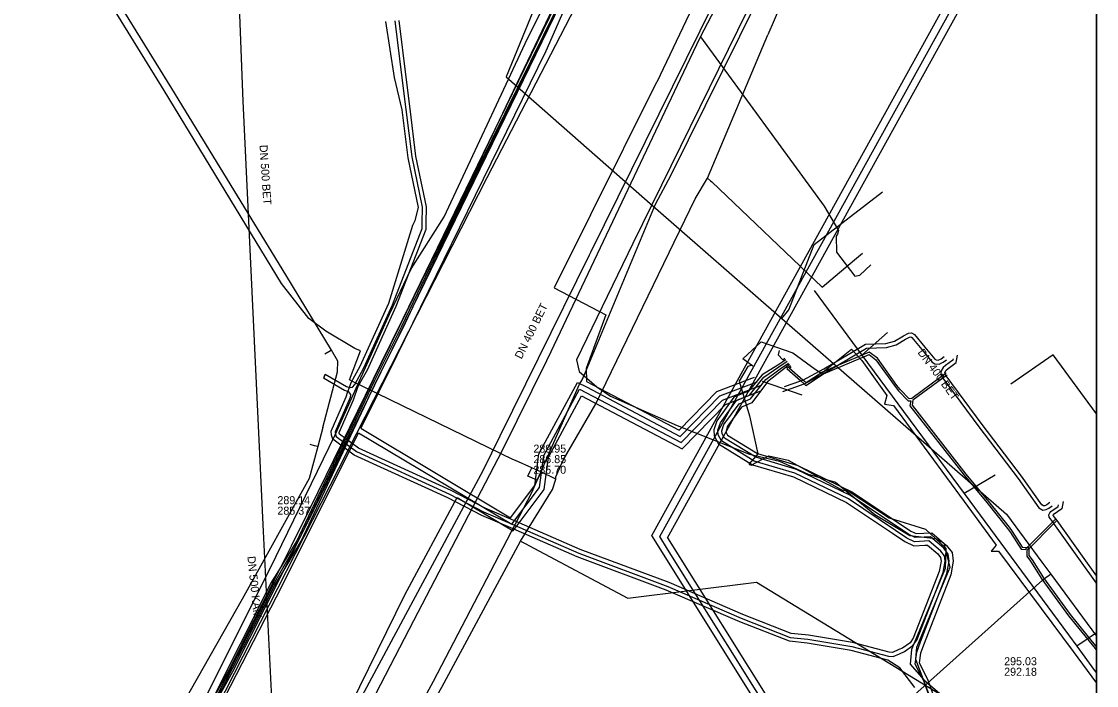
# Model space of a CAD drawing. Extents: x -598233 to -596890, y -1157848 to -1156431.
# Drawn here: x -596997.9 to -596890.5, y -1156890.3 to -1156824 of the extents above; entities that cross this region are included whole.
import ezdxf

# ---------------------------------------------------------------- set-up
doc = ezdxf.new("R2010")
doc.units = 0
for name, color, linetype in [('Vrstva 12', 7, 'Continuous'), ('Vrstva 13', 7, 'Continuous'), ('Vrstva 19', 7, 'Continuous'), ('Vrstva 25', 7, 'Continuous'), ('Vrstva 26', 7, 'Continuous'), ('Vrstva 37', 7, 'Continuous'), ('Vrstva 42', 7, 'Continuous'), ('Vrstva 44', 7, 'Continuous'), ('Vrstva 55', 7, 'Continuous'), ('Vrstva 58', 7, 'Continuous'), ('Vrstva 60', 7, 'Continuous'), ('Vrstva 9', 7, 'Continuous'), ('zajmove_uzemi', 7, 'Continuous')]:
    doc.layers.add(name, color=color, linetype=linetype)

msp = doc.modelspace()

# ---------------------------------------------------------------- linework, layer by layer
at = {"layer": 'Vrstva 12'}
for points in [[(-596930.04, -1156825.5), (-596919.76, -1156805.9), (-596915.21, -1156798.19), (-596910.25, -1156789.71), (-596903.15, -1156779.71)], [(-596963.84, -1156893.76), (-596958.67, -1156883.83), (-596949.82, -1156866.8), (-596945.38, -1156857.84), (-596944.95, -1156856.94), (-596931.11, -1156827.75), (-596930.04, -1156825.5)], [(-596930.04, -1156825.5), (-596917.68, -1156842.43), (-596916.25, -1156844.85)], [(-596916.25, -1156844.85), (-596916.35, -1156845.24)], [(-596916.35, -1156845.24), (-596916.49, -1156845.42), (-596916.43, -1156847.03), (-596914.6, -1156849.41), (-596914.12, -1156849.32), (-596913.02, -1156848.28)]]:
    msp.add_lwpolyline(points, dxfattribs=at)
at = {"layer": 'Vrstva 13'}
for p, q in [((-596966.91, -1156856.8), (-596967.18, -1156856.98)), ((-596967.18, -1156856.98), (-596967.58, -1156857.23)), ((-596968.59, -1156866.37), (-596969.05, -1156866.25)), ((-596968.28, -1156866.45), (-596968.59, -1156866.37))]:
    msp.add_line(p, q, dxfattribs=at)
for points in [[(-596938.76, -1156803.44), (-596938.92, -1156803.8), (-596947.54, -1156824.9), (-596949.46, -1156829.5), (-596934.8, -1156842.4)], [(-596967.78, -1156864.53), (-596966.32, -1156858.99), (-596966.27, -1156857.91), (-596966.91, -1156856.8), (-596971.48, -1156849.28), (-596982.85, -1156830.68), (-596992.24, -1156815.47)], [(-596921.9, -1156853.64), (-596921.2, -1156852.79), (-596918.66, -1156846.27), (-596911.84, -1156841.01)], [(-596934.8, -1156842.4), (-596921.9, -1156853.64), (-596899.46, -1156873.19), (-596895.91, -1156878), (-596895.03, -1156879.2), (-596890.46, -1156885.4)], [(-596967.78, -1156864.53), (-596968.28, -1156866.45), (-596969.12, -1156869.63), (-596975.82, -1156881.68), (-596987.36, -1156902), (-596995.97, -1156916.01), (-597005.76, -1156929.74), (-597017.4, -1156942.73), (-597033.49, -1156958.74), (-597059.77, -1156983.91), (-597076.36, -1156999.81), (-597090.23, -1157012.97), (-597109.08, -1157030.59), (-597111.35, -1157034.13), (-597112.48, -1157035.47), (-597112.98, -1157036.09)], [(-596895.03, -1156879.2), (-596895.19, -1156879.31), (-596895.86, -1156879.78), (-596910.55, -1156892.94)]]:
    msp.add_lwpolyline(points, dxfattribs=at)
at = {"layer": 'Vrstva 19'}
for points in [[(-596890.46, -1156772.16), (-596894.96, -1156777.24), (-596902.9, -1156787.67), (-596916.35, -1156810.75), (-596921.34, -1156820.69), (-596921.42, -1156820.88), (-596923.29, -1156825.32)], [(-596948.53, -1156867.85), (-596948.8, -1156867.73), (-596964.74, -1156859.99), (-596965.12, -1156859.79), (-596963.99, -1156856.87), (-596964.57, -1156856.65), (-596967.48, -1156854.93), (-596969.17, -1156853.66), (-596971.89, -1156850.17), (-596983.64, -1156830.87), (-596992.65, -1156816.23), (-597003.25, -1156798.44), (-597029.14, -1156797.81), (-597057.59, -1156797.99), (-597061.06, -1156797.77), (-597071.98, -1156796.79), (-597087.41, -1156795.86), (-597102.05, -1156795.07), (-597103.22, -1156797.72)], [(-596944.5, -1156869.71), (-596944.5, -1156869.48), (-596943.75, -1156867.82), (-596940.5, -1156862.16), (-596930.57, -1156841.71), (-596929.34, -1156839.64), (-596923.29, -1156825.32)], [(-596929.34, -1156839.64), (-596929.02, -1156839.89), (-596928.91, -1156839.99), (-596917.88, -1156850.52), (-596914.63, -1156847.8)], [(-596914.63, -1156847.8), (-596913.85, -1156847.14)], [(-596946.45, -1156868.78), (-596946.9, -1156868.57), (-596948.53, -1156867.85)], [(-596945.99, -1156868.98), (-596946.17, -1156869.39), (-596946.36, -1156869.8), (-596947.27, -1156869.4), (-596947.09, -1156868.98), (-596946.9, -1156868.57)], [(-596944.5, -1156869.71), (-596945.99, -1156868.98), (-596946.45, -1156868.78)], [(-597070.67, -1157028.24), (-597069.06, -1157026.66), (-597068.04, -1157025.67), (-597047.41, -1157005.47), (-596990.41, -1156944.69), (-596980.1, -1156930.5), (-596969.41, -1156912.52), (-596962.33, -1156901.94), (-596955.88, -1156890.47), (-596948.03, -1156875.88), (-596944.82, -1156870.73), (-596944.5, -1156869.71)], [(-596948.03, -1156875.88), (-596947.63, -1156876.1)], [(-596947.63, -1156876.1), (-596947.41, -1156876.21)], [(-596947.41, -1156876.21), (-596947.19, -1156876.33)], [(-596947.19, -1156876.33), (-596937.31, -1156881.6), (-596924.45, -1156879.98), (-596904.63, -1156892.09), (-596901.11, -1156896.6), (-596899.26, -1156898.5), (-596890.46, -1156911.36)]]:
    msp.add_lwpolyline(points, dxfattribs=at)
at = {"layer": 'Vrstva 25'}
msp.add_line((-596934.11, -1156875.44), (-596903.03, -1156819.22), dxfattribs=at)
msp.add_lwpolyline([(-596921.58, -1156895.47), (-596933.32, -1156876.7), (-596934.11, -1156875.44)], dxfattribs=at)
at = {"layer": 'Vrstva 26'}
for p, q in [((-596934.89, -1156875.32), (-596903.33, -1156818.2)), ((-596933.32, -1156875.57), (-596902.74, -1156820.24)), ((-596921.74, -1156896.34), (-596934.89, -1156875.32)), ((-596933.32, -1156875.57), (-596921.41, -1156894.6))]:
    msp.add_line(p, q, dxfattribs=at)
at = {"layer": 'Vrstva 37'}
msp.add_lwpolyline([(-596890.46, -1156863.18), (-596894.78, -1156857.28), (-596899.01, -1156860.21)], dxfattribs=at)
at = {"layer": 'Vrstva 42'}
for points in [[(-596967.62, -1156859.4), (-596967.54, -1156859.22), (-596965.4, -1156860.46), (-596965.12, -1156860.54), (-596965.04, -1156860.56), (-596964.79, -1156860.51), (-596964.58, -1156860.23), (-596963.67, -1156858.59), (-596960.8, -1156852.28), (-596957.85, -1156844.66), (-596957.85, -1156844.13), (-596957.8, -1156842.53), (-596958.86, -1156837.52), (-596959.44, -1156832.77), (-596959.85, -1156829.61), (-596960.54, -1156823.91)], [(-596910.21, -1156886.73), (-596910.84, -1156887.01), (-596911.17, -1156886.98), (-596914.83, -1156886.03), (-596919.25, -1156885.3), (-596920.96, -1156885.11), (-596925.81, -1156883.22), (-596933.16, -1156880.04), (-596942.04, -1156876.72), (-596948.68, -1156873.84), (-596951.55, -1156872.61), (-596954.93, -1156870.85), (-596964.22, -1156866.61), (-596966.1, -1156865.2), (-596966.13, -1156865.11), (-596966.14, -1156865.04), (-596964.71, -1156861.77), (-596964.24, -1156860.42), (-596963.32, -1156858.77), (-596960.43, -1156852.43), (-596957.45, -1156844.74), (-596957.45, -1156844.13), (-596957.4, -1156842.49), (-596958.47, -1156837.45), (-596959.05, -1156832.72), (-596959.45, -1156829.56), (-596960.14, -1156823.88)], [(-596959.26, -1156837.59), (-596959.84, -1156832.82), (-596960.6, -1156829.58), (-596961.49, -1156823.97)], [(-596908.6, -1156890.52), (-596910.1, -1156888.56), (-596911.3, -1156887.78), (-596914.99, -1156886.81), (-596919.36, -1156886.09), (-596921.15, -1156885.9), (-596926.11, -1156883.96), (-596933.46, -1156880.79), (-596942.34, -1156877.46), (-596949, -1156874.57), (-596951.89, -1156873.34), (-596955.28, -1156871.57), (-596964.63, -1156867.3), (-596966.76, -1156865.7), (-596966.91, -1156865.3), (-596966.95, -1156864.92), (-596965.45, -1156861.48), (-596965.26, -1156860.95), (-596965.12, -1156860.54), (-596964.94, -1156860.03), (-596964.03, -1156858.4), (-596961.17, -1156852.12), (-596958.77, -1156844.32), (-596958.53, -1156843.87), (-596958.2, -1156842.56), (-596959.26, -1156837.59)], [(-596921.79, -1156860.93), (-596919.67, -1156860.19), (-596919.63, -1156860.18), (-596917.5, -1156859.02), (-596916.49, -1156858.43), (-596914.9, -1156857.49), (-596913.43, -1156856.62), (-596911.46, -1156856.54), (-596910.48, -1156856.28), (-596909.56, -1156855.72), (-596909.14, -1156855.52), (-596909.03, -1156855.5), (-596908.92, -1156855.56), (-596907.92, -1156856.76), (-596906.88, -1156858.01), (-596906.62, -1156858.17), (-596906.19, -1156858.21), (-596905.79, -1156858.02), (-596905.44, -1156857.77)], [(-596921.65, -1156860.46), (-596920.01, -1156859.89), (-596919.8, -1156859.81), (-596919.8, -1156859.81), (-596917.7, -1156858.68), (-596915.1, -1156857.14), (-596913.55, -1156856.22), (-596911.51, -1156856.14), (-596910.64, -1156855.91), (-596909.75, -1156855.37), (-596909.26, -1156855.13), (-596908.96, -1156855.08), (-596908.66, -1156855.24), (-596907.61, -1156856.5), (-596906.61, -1156857.7), (-596906.49, -1156857.78), (-596906.27, -1156857.8), (-596905.99, -1156857.67), (-596905.68, -1156857.45)], [(-596922.18, -1156856.84), (-596922.28, -1156857.29), (-596921.82, -1156857.79), (-596921.6, -1156857.63)], [(-596921.49, -1156857.78), (-596922.32, -1156858.3)], [(-596922.2, -1156858.49), (-596921.37, -1156857.93)], [(-596921.05, -1156858.37), (-596921.42, -1156858.64), (-596920.01, -1156859.89), (-596919.67, -1156860.19), (-596919.5, -1156860.34), (-596917.75, -1156859.18), (-596913.19, -1156857.24), (-596912.5, -1156857.77), (-596910.57, -1156860.45), (-596910.24, -1156860.87), (-596909.27, -1156861.89), (-596909.01, -1156861.87), (-596909.11, -1156862.38), (-596903.68, -1156869.31), (-596901.43, -1156872.04), (-596899.34, -1156874.63), (-596899.05, -1156875.04), (-596898, -1156876.71), (-596897.57, -1156876.72), (-596897.38, -1156876.53), (-596894.83, -1156873.97), (-596894.6, -1156873.74)], [(-596905.49, -1156859.11), (-596905.6, -1156859.19), (-596905.94, -1156859.45), (-596908.93, -1156861.66), (-596909.19, -1156861.69), (-596910.08, -1156860.73), (-596910.41, -1156860.33), (-596912.36, -1156857.63), (-596913.17, -1156857.01), (-596916.49, -1156858.43), (-596917.85, -1156859), (-596919.48, -1156860.09), (-596919.8, -1156859.81), (-596921.16, -1156858.6), (-596920.98, -1156858.48)], [(-596904.8, -1156857.67), (-596904.83, -1156857.82), (-596905.56, -1156858.34), (-596905.78, -1156858.56), (-596906.03, -1156858.95), (-596905.98, -1156859.39), (-596905.94, -1156859.45), (-596905.82, -1156859.61), (-596902.21, -1156864.47), (-596898.28, -1156869.63), (-596896.22, -1156872.56), (-596895.83, -1156872.8), (-596895.48, -1156872.73), (-596895.24, -1156872.61), (-596894.89, -1156872.36)], [(-596895.13, -1156872.04), (-596895.44, -1156872.27), (-596895.61, -1156872.35), (-596895.75, -1156872.37), (-596895.94, -1156872.26), (-596897.95, -1156869.39), (-596901.89, -1156864.23), (-596905.5, -1156859.37), (-596905.6, -1156859.24), (-596905.6, -1156859.19), (-596905.62, -1156859.05), (-596905.47, -1156858.81), (-596905.3, -1156858.65), (-596904.47, -1156858.06), (-596904.34, -1156857.33)], [(-596922.32, -1156858.3), (-596923.86, -1156859.27), (-596925.25, -1156860.91), (-596926.69, -1156861.52), (-596928.41, -1156863.87), (-596928.69, -1156864.76), (-596928.67, -1156865.38), (-596928.22, -1156866.16), (-596924.84, -1156868.26), (-596920.73, -1156869.47), (-596915.44, -1156872.03), (-596910.85, -1156875.11)], [(-596910.56, -1156874.82), (-596915.24, -1156871.68), (-596920.59, -1156869.09), (-596924.68, -1156867.89), (-596927.92, -1156865.87), (-596928.27, -1156865.27), (-596928.29, -1156864.81), (-596928.05, -1156864.06), (-596926.43, -1156861.85), (-596925.14, -1156861.3), (-596923.69, -1156859.5), (-596922.2, -1156858.49)], [(-596907.11, -1156891.56), (-596907.72, -1156889.83), (-596908.57, -1156888.18), (-596908.4, -1156886.98), (-596908.06, -1156885.96), (-596905.41, -1156879.14), (-596905.18, -1156877.89), (-596905.28, -1156877.2), (-596905.73, -1156876.61), (-596907.06, -1156875.46), (-596907.68, -1156875.5), (-596908.57, -1156875.54), (-596909.21, -1156875.24), (-596915.04, -1156871.33), (-596920.44, -1156868.72), (-596924.51, -1156867.52), (-596927.63, -1156865.59), (-596927.87, -1156865.16), (-596927.89, -1156864.86), (-596927.69, -1156864.24), (-596926.17, -1156862.17), (-596925.02, -1156861.68), (-596923.52, -1156859.74), (-596922.06, -1156858.69)], [(-596921.94, -1156858.87), (-596923.35, -1156859.97), (-596924.91, -1156862.07), (-596925.92, -1156862.5), (-596927.33, -1156864.42), (-596927.48, -1156864.92), (-596927.48, -1156865.04), (-596927.33, -1156865.3), (-596924.35, -1156867.15), (-596920.3, -1156868.34), (-596914.84, -1156870.99), (-596909.02, -1156874.89), (-596908.49, -1156875.14), (-596907.7, -1156875.1), (-596906.93, -1156875.05), (-596905.44, -1156876.33), (-596904.9, -1156877.04), (-596904.77, -1156877.9), (-596905.02, -1156879.25), (-596907.69, -1156886.11), (-596908.04, -1156887.07), (-596908.18, -1156888.06), (-596907.36, -1156889.67), (-596906.72, -1156891.46)], [(-596922.06, -1156858.69), (-596921.25, -1156858.1)], [(-596921.15, -1156858.24), (-596921.94, -1156858.87)], [(-596967.62, -1156859.4), (-596967.71, -1156859.58), (-596965.6, -1156860.81), (-596965.26, -1156860.95), (-596965.24, -1156860.95), (-596964.99, -1156861.24), (-596965.04, -1156861.53), (-596966.54, -1156864.98), (-596966.52, -1156865.21), (-596966.43, -1156865.45), (-596964.42, -1156866.95), (-596955.11, -1156871.21), (-596951.72, -1156872.98), (-596948.84, -1156874.2), (-596942.19, -1156877.09), (-596933.31, -1156880.41), (-596925.96, -1156883.59), (-596921.06, -1156885.51), (-596919.31, -1156885.7), (-596914.91, -1156886.42), (-596911.23, -1156887.38), (-596910.77, -1156887.41), (-596910.15, -1156887.14)], [(-596905.37, -1156859.27), (-596905.5, -1156859.37), (-596905.82, -1156859.61), (-596908.8, -1156861.82), (-596908.89, -1156862.32), (-596903.52, -1156869.19), (-596901.27, -1156871.92), (-596899.18, -1156874.51), (-596898.88, -1156874.93), (-596897.88, -1156876.51), (-596897.38, -1156876.53), (-596897.24, -1156876.53), (-596897.24, -1156876.67), (-596897.24, -1156877.32), (-596896.89, -1156877.77), (-596895.76, -1156879.57), (-596893.09, -1156883.23), (-596890.46, -1156886.48)], [(-596893.78, -1156871.92), (-596893.91, -1156872.65), (-596894.8, -1156873.28), (-596894.82, -1156873.32), (-596894.81, -1156873.34), (-596894.43, -1156873.83), (-596891.9, -1156877.39), (-596890.46, -1156879.4)], [(-596890.46, -1156880.09), (-596892.22, -1156877.62), (-596894.71, -1156874.13), (-596894.76, -1156874.07), (-596894.83, -1156873.97), (-596895.19, -1156873.51), (-596895.23, -1156873.28), (-596895.14, -1156873.05), (-596895.01, -1156872.94), (-596894.28, -1156872.42), (-596894.25, -1156872.26)], [(-596894.48, -1156873.9), (-596894.71, -1156874.13), (-596897.24, -1156876.67), (-596897.27, -1156876.71), (-596897.44, -1156876.83), (-596897.44, -1156877.39), (-596897.05, -1156877.89), (-596895.92, -1156879.69), (-596893.25, -1156883.35), (-596890.61, -1156886.62), (-596890.46, -1156886.82)], [(-596910.85, -1156875.11), (-596909.61, -1156875.94), (-596908.73, -1156876.35), (-596907.63, -1156876.3), (-596907.34, -1156876.28), (-596906.32, -1156877.16), (-596906.04, -1156877.52), (-596905.99, -1156877.88), (-596906.18, -1156878.92), (-596908.78, -1156885.6), (-596909.08, -1156886.05), (-596909.85, -1156886.57), (-596910.21, -1156886.73)], [(-596910.15, -1156887.14), (-596909.66, -1156886.92), (-596908.8, -1156886.33), (-596908.42, -1156885.78), (-596905.79, -1156879.03), (-596905.58, -1156877.89), (-596905.66, -1156877.36), (-596906.03, -1156876.89), (-596907.2, -1156875.87), (-596907.66, -1156875.9), (-596908.65, -1156875.95), (-596909.41, -1156875.59), (-596910.56, -1156874.82)]]:
    msp.add_lwpolyline(points, dxfattribs=at)
at = {"layer": 'Vrstva 44'}
for points in [[(-596890.46, -1156743.11), (-596892.15, -1156744.61), (-596895.18, -1156746.76), (-596895.8, -1156747.2), (-596900.47, -1156750.5), (-596907.89, -1156759.47), (-596909.32, -1156761.2), (-596909.66, -1156761.95), (-596911.44, -1156765.86), (-596919.75, -1156778.42), (-596930.98, -1156796.03), (-596943.95, -1156822.05), (-596944.17, -1156822.49), (-596944.65, -1156823.48), (-596958.23, -1156851.4), (-596959.43, -1156853.86), (-596961.6, -1156858.27)], [(-597074.66, -1157004.75), (-597063.06, -1156993.3), (-597054.52, -1156985.37), (-597042.87, -1156973.56), (-597038.02, -1156968.83), (-597030.03, -1156960.43), (-597028.88, -1156959.17), (-597028.54, -1156958.8), (-597028.27, -1156958.51), (-597018, -1156947.32), (-597008.96, -1156936.55), (-596993.33, -1156915.45), (-596979.36, -1156891.26), (-596973.04, -1156878.64), (-596966.53, -1156865.27), (-596961.1, -1156853.21), (-596958.95, -1156848.68), (-596955.64, -1156843.49), (-596947.56, -1156826.18), (-596941.41, -1156813.85)], [(-596944.53, -1156822.31), (-596949.46, -1156832.45), (-596959.79, -1156853.68), (-596961.95, -1156858.09), (-596969.07, -1156872.62), (-596970.93, -1156876.38), (-596972.18, -1156878.86), (-596977.16, -1156888.77), (-596979.04, -1156892.19), (-596981.07, -1156895.9), (-596981.43, -1156896.54), (-596984.97, -1156902.83), (-596987.13, -1156906.65), (-596989.83, -1156911.32), (-596991.25, -1156913.77), (-596991.64, -1156914.44), (-596992.14, -1156915.09), (-596993.84, -1156917.29), (-597017.56, -1156947.92)], [(-597003.68, -1156931.84), (-596997.33, -1156922.45), (-596993.84, -1156917.29), (-596990.74, -1156912.71), (-596988.54, -1156908.45), (-596981.43, -1156896.54), (-596980.13, -1156894.36), (-596979.04, -1156892.19), (-596972.96, -1156880.14), (-596972.18, -1156878.86), (-596970.39, -1156875.95), (-596962.71, -1156859.73), (-596960.15, -1156854.51), (-596953.53, -1156840.96), (-596949.46, -1156832.45), (-596944.76, -1156822.63)], [(-596944.46, -1156822.77), (-596953.45, -1156841), (-596959.94, -1156854.53), (-596962.62, -1156859.85), (-596970.21, -1156875.83), (-596970.23, -1156875.88), (-596970.24, -1156875.89), (-596972.73, -1156880.25), (-596979.93, -1156894.44), (-596984.97, -1156902.83), (-596988.35, -1156908.44), (-596989.83, -1156911.32), (-596990.58, -1156912.78), (-596991.25, -1156913.77), (-596992.14, -1156915.09), (-596995.59, -1156920.2), (-597003.51, -1156931.93)], [(-597003.37, -1156932.06), (-596994.69, -1156919.04), (-596990.54, -1156912.82), (-596988.16, -1156908.55), (-596980.77, -1156896.18), (-596979.79, -1156894.54), (-596978.85, -1156892.69), (-596972.61, -1156880.36), (-596971.78, -1156878.98), (-596969.94, -1156875.89), (-596962.6, -1156860.31), (-596962.36, -1156859.82), (-596961.96, -1156859.02), (-596959.75, -1156854.6), (-596958.23, -1156851.4), (-596953.34, -1156841.05), (-596944.65, -1156823.48)], [(-596925.38, -1156822.92), (-596936.78, -1156846.16), (-596942.41, -1156857.77), (-596942.17, -1156858.96), (-596940.38, -1156860.47), (-596939.02, -1156861.42), (-596932.36, -1156864.34), (-596925.14, -1156867.19), (-596922.14, -1156867.92), (-596919.27, -1156869.2), (-596916.54, -1156869.99), (-596912.6, -1156873.22), (-596909.12, -1156875.34), (-596906.56, -1156875.63), (-596905.71, -1156876.1), (-596905.13, -1156878.51), (-596908.45, -1156886.53), (-596908.55, -1156887.68), (-596906.97, -1156891.82), (-596906.94, -1156893.28), (-596907.71, -1156895.4), (-596907.59, -1156896.78), (-596896.5, -1156911.33), (-596890.46, -1156919.1)], [(-596961.6, -1156858.27), (-596961.96, -1156859.02), (-596962.6, -1156860.31), (-596968.71, -1156872.79), (-596970.21, -1156875.83), (-596970.24, -1156875.89), (-596970.57, -1156876.55), (-596971.78, -1156878.98), (-596976.81, -1156888.96), (-596978.85, -1156892.69), (-596980.72, -1156896.1), (-596980.77, -1156896.18), (-596986.78, -1156906.85), (-596991.3, -1156914.67), (-596994.69, -1156919.04), (-596995.59, -1156920.2), (-596997.33, -1156922.45), (-597007.93, -1156936.13)]]:
    msp.add_lwpolyline(points, dxfattribs=at)
at = {"layer": 'Vrstva 55'}
for points in [[(-596890.46, -1156743.5), (-596892.46, -1156745.21), (-596897.51, -1156748.88), (-596902.28, -1156749.44), (-596910.8, -1156758.94), (-596909.82, -1156764.19), (-596911.64, -1156768.32), (-596919.59, -1156779.1), (-596928.14, -1156792.56), (-596937.72, -1156809.23), (-596945.5, -1156826.96), (-596952.56, -1156841.37), (-596960.38, -1156857.36), (-596963.98, -1156864.61), (-596949.01, -1156873.55), (-596946.6, -1156870.34), (-596946.19, -1156867.18), (-596942.32, -1156860.03), (-596941.43, -1156860.49), (-596932.08, -1156865.43), (-596928.1, -1156861.38), (-596924.38, -1156859.99)], [(-596890.46, -1156764.45), (-596896.53, -1156772.16), (-596899.38, -1156772.57), (-596902.37, -1156774.57), (-596904.03, -1156776.92), (-596910.58, -1156785.84), (-596919.4, -1156800.43), (-596925.34, -1156810.98), (-596934.39, -1156830.06), (-596934.45, -1156830.1), (-596941.03, -1156843.3), (-596944.64, -1156850.58), (-596939.5, -1156853.27), (-596941.45, -1156858.66), (-596941.44, -1156859.93), (-596932.17, -1156864.82), (-596928.39, -1156860.96), (-596924.65, -1156859.52)], [(-596924.8, -1156858.42), (-596925.8, -1156857.67), (-596923.98, -1156855.99), (-596920.8, -1156857.08), (-596918.56, -1156858.73), (-596917.95, -1156859.1), (-596914.95, -1156856.71), (-596913.91, -1156857.84), (-596911.42, -1156861.35), (-596911.64, -1156862.21), (-596910.74, -1156862.34), (-596903.68, -1156871.93), (-596900.5, -1156876.3), (-596900.98, -1156876.91), (-596900.24, -1156876.88), (-596892.8, -1156886.92), (-596890.46, -1156890.08)], [(-596924.99, -1156858.36), (-596925.29, -1156858.45), (-596926.16, -1156859.91), (-596925.14, -1156863.39), (-596924.3, -1156867.16), (-596925.19, -1156868.19), (-596924.96, -1156868.3), (-596923.21, -1156867.38), (-596921.26, -1156867.82), (-596915.73, -1156870.88), (-596915.48, -1156870.75), (-596911.17, -1156873.56), (-596907.56, -1156874.7), (-596905.53, -1156876.58), (-596905.57, -1156878.63), (-596908.53, -1156885.68), (-596908.95, -1156886.73), (-596909.08, -1156888.19), (-596907.7, -1156889.74), (-596904.58, -1156892.41)], [(-596919.86, -1156861.32), (-596923.83, -1156859.94)], [(-597069.74, -1157001.91), (-597055.17, -1156987.92), (-597045.1, -1156978.26), (-597030.18, -1156963.14), (-597019.16, -1156951.4), (-597007.83, -1156938.34), (-597000.27, -1156928.35), (-596991.63, -1156916.64), (-596988.25, -1156910.28), (-596981.73, -1156899.08), (-596978.12, -1156892.58), (-596971.83, -1156880.35), (-596964.21, -1156865.06), (-596948.88, -1156874.21), (-596946.12, -1156870.53), (-596945.7, -1156867.33), (-596942.11, -1156860.7), (-596931.98, -1156866.05), (-596927.82, -1156861.81), (-596924.03, -1156860.35)], [(-596948.75, -1156874.87), (-596945.64, -1156870.73), (-596945.22, -1156867.49), (-596941.91, -1156861.37), (-596931.88, -1156866.67), (-596927.54, -1156862.24), (-596924, -1156860.87)], [(-597058.24, -1157007.55), (-597045.07, -1156994.34), (-597034.55, -1156984.29), (-597020.7, -1156970.03), (-597009.79, -1156958.24), (-596997.15, -1156943.42), (-596987.85, -1156931.37), (-596977.1, -1156914.45), (-596969.49, -1156901.48), (-596959.56, -1156881.26), (-596954.35, -1156871.52), (-596948.75, -1156874.87)]]:
    msp.add_lwpolyline(points, dxfattribs=at)
at = {"layer": 'Vrstva 58'}
for points in [[(-597115.64, -1157042.19), (-597035.06, -1156963.83), (-597023.86, -1156959.57), (-596991.41, -1156918.15), (-596951.34, -1156839.56), (-596924.93, -1156788.51), (-596911.05, -1156767.47), (-596898.61, -1156749.4), (-596890.46, -1156742.24)], [(-597086.88, -1157045.18), (-597086.58, -1157044.59), (-597066.89, -1157025.23), (-597051.01, -1157009.31), (-597046.7, -1157005.01), (-597026.73, -1156985.36), (-597011.58, -1156970.08), (-596991.8, -1156947.93), (-596989.15, -1156945.07), (-596988.35, -1156943.93), (-596988.21, -1156942.76), (-596974.88, -1156923.46), (-596956.71, -1156889.88), (-596946.89, -1156871.03), (-596942.11, -1156860.2), (-596941.85, -1156859.79), (-596941.53, -1156859.01), (-596934.53, -1156842.22), (-596932.96, -1156839.31), (-596920.95, -1156815.01), (-596913.39, -1156801.07), (-596903.8, -1156786.32), (-596893.16, -1156776.74), (-596890.46, -1156773.58)]]:
    msp.add_lwpolyline(points, dxfattribs=at)
at = {"layer": 'Vrstva 60'}
msp.add_lwpolyline([(-596890.46, -1157848.46), (-596890.46, -1156430.86)], dxfattribs=at)
at = {"layer": 'Vrstva 9'}
for p, q in [((-596977.2, -1156792.15), (-596975.78, -1156831.94)), ((-596975.78, -1156831.94), (-596973.74, -1156874.94)), ((-596911.33, -1156855.04), (-596913.9, -1156857.33)), ((-596951.75, -1156868.81), (-596967.47, -1156898.07)), ((-596900.59, -1156869.3), (-596903.7, -1156871.13)), ((-596890.46, -1156885.04), (-596892.43, -1156886.39))]:
    msp.add_line(p, q, dxfattribs=at)
for points in [[(-596927.36, -1156819.38), (-596941.03, -1156847.07), (-596941.15, -1156847.31), (-596950.07, -1156865.4), (-596950.07, -1156865.4), (-596951.75, -1156868.81)], [(-596918.68, -1156850.86), (-596913.9, -1156857.32), (-596913.9, -1156857.33), (-596903.7, -1156871.12), (-596893.25, -1156885.26)], [(-596973.74, -1156874.94), (-596972.6, -1156897.57), (-596972.33, -1156898.78)], [(-596893.25, -1156885.26), (-596892.43, -1156886.39), (-596890.67, -1156888.81), (-596890.46, -1156889.09)]]:
    msp.add_lwpolyline(points, dxfattribs=at)
at = {"layer": 'zajmove_uzemi'}
msp.add_lwpolyline([(-598232.89, -1156430.86), (-596890.46, -1156430.86), (-596890.46, -1157848.46), (-598232.89, -1157848.46)], close=True, dxfattribs=at)

# ---------------------------------------------------------------- texts
at = {"layer": 'Vrstva 12'}
for s, rotation, p in [('DN 500 BET', 273.8028, (-596974.1, -1156836.33)), ('DN 400 BET', 63.7702, (-596947.92, -1156857.77)), ('DN 400 BET', 306.4751, (-596908.38, -1156857.06)), ('DN 500 KAM', 275.8998, (-596975.31, -1156877.43))]:
    msp.add_text(s, height=0.8, rotation=rotation, dxfattribs=at).set_placement(p)
for s, p in [('289.95', (-596946.73, -1156867.05)), ('286.85', (-596946.73, -1156868.1)), ('285.70', (-596946.73, -1156869.16)), ('289.14', (-596972.31, -1156872.2)), ('285.37', (-596972.31, -1156873.25)), ('295.03', (-596899.69, -1156888.29)), ('292.18', (-596899.69, -1156889.34))]:
    msp.add_text(s, height=0.8, dxfattribs=at).set_placement(p)

doc.saveas('drawing.dxf')
